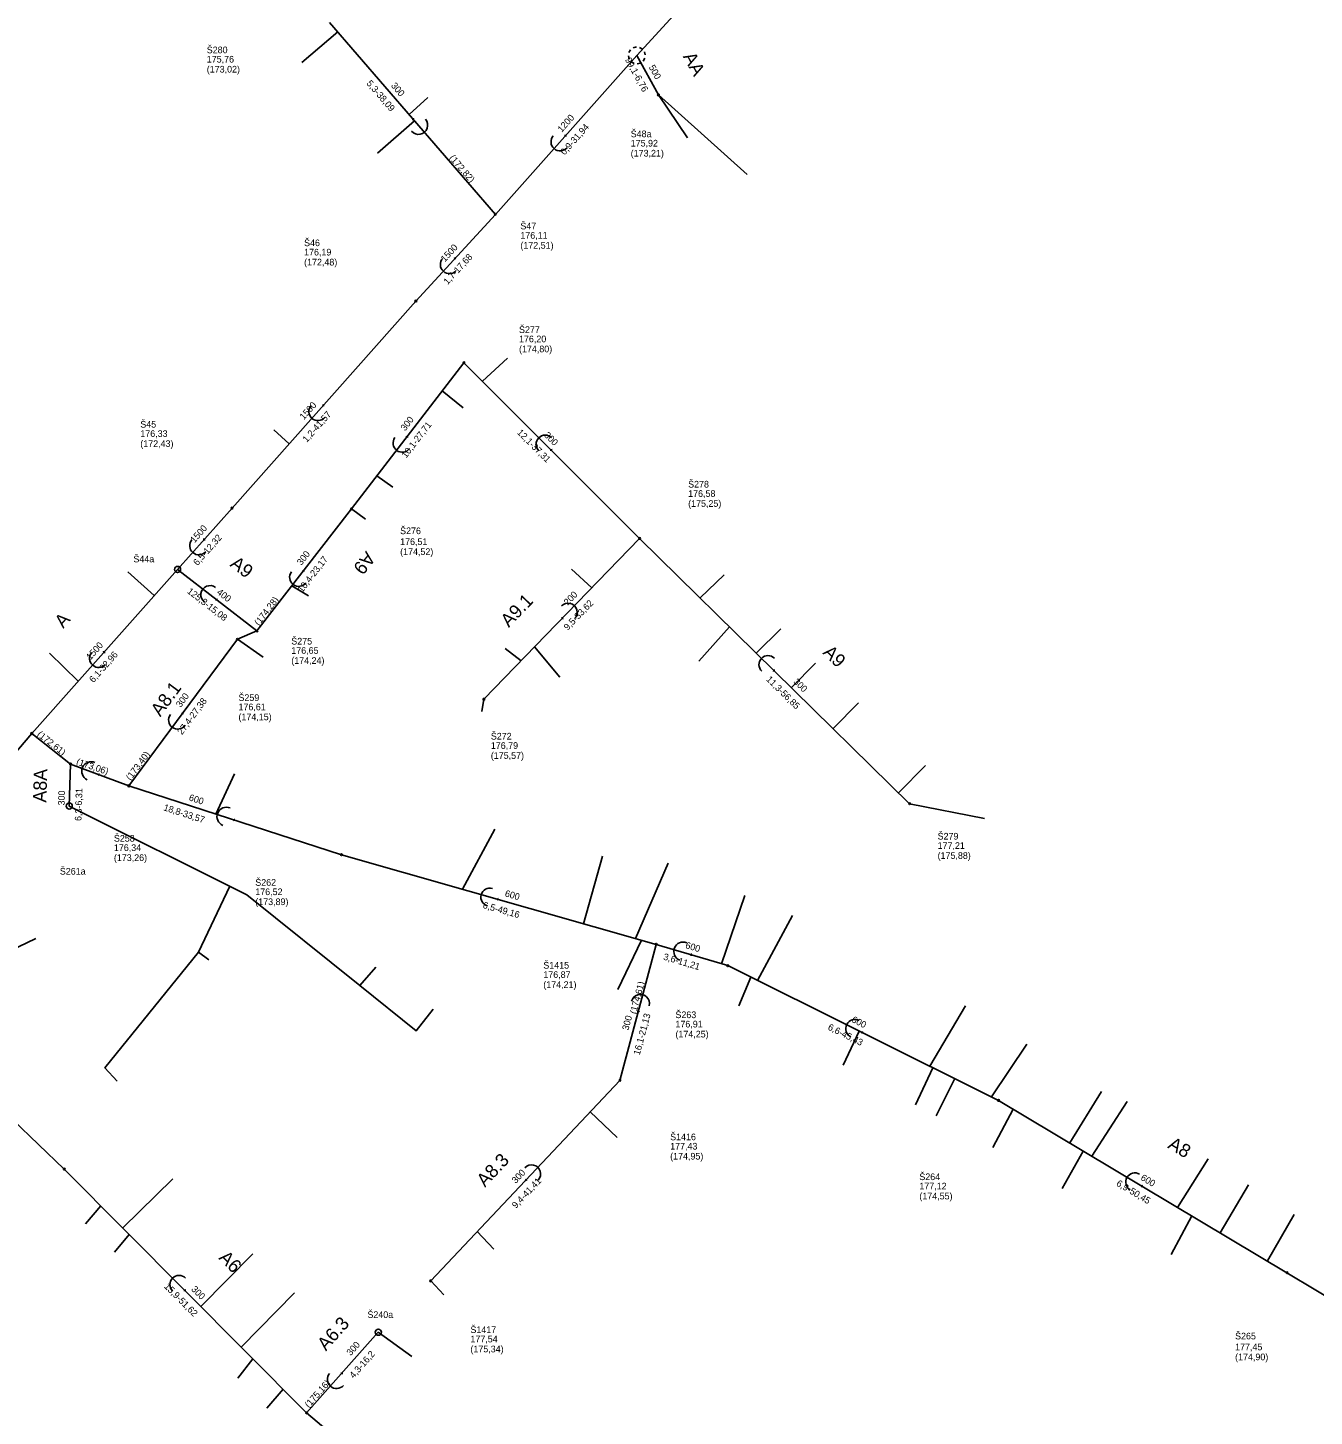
# Model space of a CAD drawing. Extents: x -548529 to -543591, y -1201432 to -1192608.
# Drawn here: x -544328 to -544134.8, y -1193048.7 to -1192840.3 of the extents above; entities that cross this region are included whole.
import ezdxf

# ---------------------------------------------------------------- set-up
doc = ezdxf.new("R2010")
doc.units = 0
for name, color, linetype in [('C3D_Bod-Značky', 7, 'Continuous'), ('C3D_Koridor', 7, 'Continuous'), ('C3D_Křižovatka', 7, 'Continuous'), ('C3D_Netisknutelná', 7, 'Continuous'), ('C3D_PP-zobrazeni v PR', 7, 'Continuous'), ('C3D_PR-Popisek', 7, 'Continuous'), ('C3D_SPR-Popisek', 7, 'Continuous'), ('C3D_Tlakove_potrubi_Popis', 7, 'Continuous'), ('C3D_ZPR-Formaty', 7, 'Continuous')]:
    doc.layers.add(name, color=color, linetype=linetype)

# ---------------------------------------------------------------- blocks, each defined once
blk = doc.blocks.new('100')
at = {"layer": 'Defpoints'}
blk.add_circle((0, 0), 0.127, dxfattribs=at)
blk = doc.blocks.new('102')
at = {"layer": 'Defpoints'}
for p, q in [((-1.17, -0.49), (-1.27, 0)), ((-1.17, 0.49), (-0.9, 0.9)), ((-0.49, 1.17), (0, 1.27)), ((0.49, 1.17), (0.9, 0.9)), ((1.17, 0.49), (1.27, 0)), ((-0.49, -1.17), (-0.9, -0.9)), ((0.49, -1.17), (0, -1.27)), ((1.17, -0.49), (0.9, -0.9))]:
    blk.add_line(p, q, dxfattribs=at)
blk = doc.blocks.new('101')
at = {"layer": 'Defpoints'}
blk.add_circle((0, 0), 0.463, dxfattribs=at)
blk = doc.blocks.new('91')
at = {"layer": 'Defpoints'}
blk.add_lwpolyline([(0.08, 0.14), (0.19, 0), (0.08, -0.14)], dxfattribs=at)
blk.add_arc((1.37, 0), 1.37, 270, 90, dxfattribs=at)
blk = doc.blocks.new('86')
at = {"layer": 'Defpoints'}
blk.add_lwpolyline([(0.08, 0.14), (0.19, 0), (0.08, -0.14)], dxfattribs=at)
blk.add_arc((1.37, 0), 1.37, 270, 90, dxfattribs=at)

msp = doc.modelspace()

# ---------------------------------------------------------------- linework, layer by layer
at = {"layer": 'C3D_Bod-Značky'}
for points in [[(-544213.325, -1192819.098), (-544236.511, -1192844.411)], [(-544282.66, -1192839.46), (-544257.75, -1192868.27)], [(-544236.511, -1192844.411), (-544257.75, -1192868.27)], [(-544233.256, -1192850.339), (-544236.511, -1192844.411)], [(-544257.75, -1192868.27), (-544269.702, -1192881.298)], [(-544269.702, -1192881.298), (-544297.304, -1192912.387)], [(-544262.47, -1192890.55), (-544279.368, -1192912.51)], [(-544236.09, -1192916.93), (-544262.47, -1192890.55)], [(-544297.304, -1192912.387), (-544305.491, -1192921.594)], [(-544279.368, -1192912.51), (-544293.566, -1192930.822)], [(-544259.476, -1192941.077), (-544236.09, -1192916.93)], [(-544195.529, -1192956.765), (-544236.09, -1192916.93)], [(-544305.491, -1192921.594), (-544327.39, -1192946.221)], [(-544293.566, -1192930.822), (-544305.491, -1192921.594)], [(-544293.566, -1192930.822), (-544296.51, -1192932.08)], [(-544296.51, -1192932.08), (-544312.81, -1192954.08)], [(-544327.39, -1192946.221), (-544355.66, -1192979.427)], [(-544321.558, -1192950.814), (-544327.39, -1192946.221)], [(-544321.759, -1192957.117), (-544321.558, -1192950.814)], [(-544312.81, -1192954.08), (-544321.558, -1192950.814)], [(-544280.876, -1192964.417), (-544312.81, -1192954.08)], [(-544233.591, -1192977.882), (-544280.876, -1192964.417)], [(-544239.04, -1192998.3), (-544233.591, -1192977.882)], [(-544222.846, -1192981.078), (-544233.591, -1192977.882)], [(-544182.172, -1193001.318), (-544222.846, -1192981.078)], [(-544322.5, -1193011.63), (-544345.72, -1192989.39)], [(-544267.47, -1193028.41), (-544239.04, -1192998.3)], [(-544138.857, -1193027.179), (-544182.172, -1193001.318)], [(-544286.1, -1193048.23), (-544322.5, -1193011.63)], [(-544095.329, -1193053.232), (-544138.857, -1193027.179)], [(-544275.341, -1193036.117), (-544286.1, -1193048.23)], [(-544277.47, -1193055.51), (-544286.1, -1193048.23)]]:
    msp.add_lwpolyline(points, dxfattribs=at)
at = {"layer": 'C3D_Koridor'}
for points in [[(-544281.437, -1192840.875), (-544286.837, -1192845.474)], [(-544233.256, -1192850.339), (-544219.943, -1192862.274)], [(-544233.256, -1192850.339), (-544228.897, -1192856.799)], [(-544270.717, -1192853.272), (-544267.878, -1192850.747)], [(-544269.899, -1192854.218), (-544275.454, -1192859.097)], [(-544259.704, -1192893.316), (-544255.956, -1192889.849)], [(-544265.727, -1192894.782), (-544262.591, -1192897.334)], [(-544288.715, -1192902.713), (-544291.047, -1192900.643)], [(-544275.549, -1192907.547), (-544273.146, -1192909.222)], [(-544279.368, -1192912.51), (-544277.276, -1192914.023)], [(-544243.255, -1192924.328), (-544246.325, -1192921.553)], [(-544308.98, -1192925.517), (-544312.965, -1192921.964)], [(-544226.984, -1192925.873), (-544223.374, -1192922.374)], [(-544288.308, -1192924.041), (-544285.802, -1192925.574)], [(-544222.588, -1192930.19), (-544227.201, -1192935.35)], [(-544218.572, -1192934.135), (-544214.893, -1192930.485)], [(-544296.51, -1192932.08), (-544292.646, -1192934.781)], [(-544253.886, -1192935.305), (-544256.298, -1192933.447)], [(-544251.877, -1192933.23), (-544248.065, -1192937.782)], [(-544320.424, -1192938.387), (-544324.702, -1192934.138)], [(-544213.278, -1192939.334), (-544209.667, -1192935.639)], [(-544259.476, -1192941.077), (-544259.811, -1192942.902)], [(-544207.04, -1192945.46), (-544203.224, -1192941.641)], [(-544299.742, -1192958.31), (-544296.938, -1192952.272)], [(-544197.198, -1192955.126), (-544193.153, -1192951.022)], [(-544195.529, -1192956.765), (-544184.267, -1192959)], [(-544321.759, -1192957.117), (-544295.103, -1192970.438), (-544278.127, -1192984.034), (-544275.696, -1192981.298)], [(-544262.689, -1192969.596), (-544257.822, -1192960.563)], [(-544244.524, -1192974.778), (-544241.642, -1192964.653)], [(-544236.703, -1192976.996), (-544231.792, -1192965.701)], [(-544297.646, -1192969.167), (-544302.359, -1192979.038), (-544300.802, -1192980.221)], [(-544223.795, -1192980.796), (-544220.308, -1192970.524)], [(-544218.368, -1192983.306), (-544213.114, -1192973.528)], [(-544337.14, -1192981.94), (-544326.769, -1192976.978)], [(-544235.789, -1192977.258), (-544239.342, -1192984.651)], [(-544302.359, -1192979.038), (-544316.408, -1192996.408), (-544314.577, -1192998.406)], [(-544278.127, -1192984.034), (-544269.629, -1192990.854), (-544267.101, -1192987.612)], [(-544219.407, -1192982.791), (-544221.168, -1192987.122)], [(-544192.502, -1192996.174), (-544187.147, -1192987.123)], [(-544203.095, -1192990.908), (-544205.54, -1192996.001)], [(-544183.256, -1193000.779), (-544177.905, -1192992.878)], [(-544192.037, -1192996.409), (-544194.649, -1193001.972)], [(-544188.752, -1192998.043), (-544191.555, -1193003.651)], [(-544171.476, -1193007.704), (-544166.718, -1192999.989)], [(-544179.959, -1193002.641), (-544183.034, -1193008.371)], [(-544168.186, -1193009.668), (-544162.837, -1193001.496)], [(-544243.524, -1193003.049), (-544239.481, -1193006.904)], [(-544169.458, -1193008.909), (-544172.61, -1193014.53)], [(-544155.282, -1193017.372), (-544150.71, -1193010.085)], [(-544313.711, -1193020.468), (-544306.192, -1193013.096)], [(-544148.875, -1193021.198), (-544144.653, -1193013.98)], [(-544317.023, -1193017.137), (-544319.3, -1193019.847)], [(-544153.171, -1193018.635), (-544156.239, -1193024.425)], [(-544141.8, -1193025.418), (-544137.798, -1193018.455)], [(-544312.737, -1193021.447), (-544314.959, -1193024.088)], [(-544260.467, -1193020.994), (-544257.989, -1193023.653)], [(-544302.009, -1193032.234), (-544294.2, -1193024.348)], [(-544267.47, -1193028.41), (-544265.49, -1193030.481)], [(-544295.92, -1193038.356), (-544287.93, -1193030.195)], [(-544275.341, -1193036.117), (-544270.281, -1193039.768)], [(-544294.182, -1193040.103), (-544296.446, -1193043.004)], [(-544289.626, -1193044.685), (-544292.057, -1193047.507)]]:
    msp.add_lwpolyline(points, dxfattribs=at)

# ---------------------------------------------------------------- block references
at = {"layer": 'C3D_PP-zobrazeni v PR'}
for name, p, xscale, yscale, rotation in [('102', (-544236.511, -1192844.411), 1.0000000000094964, 1.0000000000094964, -132.0000013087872), ('100', (-544233.256, -1192850.339), 1.0000000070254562, 1.0000000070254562, 118.99999892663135), ('100', (-544257.75, -1192868.27), 1.0000000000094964, 1.0000000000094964, -42.000001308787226), ('100', (-544269.702, -1192881.298), 1.0000000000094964, 1.0000000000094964, -132.0000013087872), ('100', (-544262.47, -1192890.55), 1.0000000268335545, 1.0000000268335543, -176.00000028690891), ('100', (-544297.304, -1192912.387), 1.0000000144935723, 1.0000000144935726, -130.99999910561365), ('100', (-544279.368, -1192912.51), 0.9999999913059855, 0.9999999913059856, -127.00000193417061), ('100', (-544236.09, -1192916.93), 1.000000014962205, 1.0000000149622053, 90.99999994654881), ('101', (-544305.491, -1192921.594), 1.0000000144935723, 1.0000000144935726, -130.99999910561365), ('100', (-544296.51, -1192932.08), 1.000000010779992, 1.0000000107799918, 38.9999989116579), ('100', (-544293.566, -1192930.822), 1.0092050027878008, 1.0092050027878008, -168.88308178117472), ('100', (-544259.476, -1192941.077), 1.0000000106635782, 1.0000000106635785, 45.99999834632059), ('100', (-544327.39, -1192946.221), 1.0000000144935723, 1.0000000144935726, -130.99999910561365), ('100', (-544321.558, -1192950.814), 1.000000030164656, 1.000000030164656, 114.99999971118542), ('100', (-544312.81, -1192954.08), 0.999999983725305, 0.999999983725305, 70.99999877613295), ('101', (-544321.759, -1192957.117), 1.000000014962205, 1.0000000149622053, -90.99999994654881), ('100', (-544195.529, -1192956.765), 1.0000000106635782, 1.0000000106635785, -44.00000165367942), ('100', (-544280.876, -1192964.417), 1.0365458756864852, 1.0365458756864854, -21.97149085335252), ('100', (-544233.591, -1192977.882), 1.019856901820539, 1.0198569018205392, 26.393983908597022), ('100', (-544222.846, -1192981.078), 1.0275072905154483, 1.027507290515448, -24.689105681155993), ('100', (-544239.04, -1192998.3), 1.0000000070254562, 1.0000000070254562, 61.000001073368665), ('100', (-544182.172, -1193001.318), 1.0072562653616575, 1.0072562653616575, 151.23333487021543), ('100', (-544322.5, -1193011.63), 1.0000000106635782, 1.0000000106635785, 135.99999834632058), ('100', (-544138.857, -1193027.179), 0.9999999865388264, 0.9999999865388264, 149.99999955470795), ('100', (-544267.47, -1193028.41), 1.00000000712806, 1.00000000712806, -133.00000056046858), ('101', (-544275.341, -1193036.117), 1.0000000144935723, 1.0000000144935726, 49.00000089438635), ('100', (-544286.1, -1193048.23), 1.0000000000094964, 1.0000000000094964, 137.9999986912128)]:
    msp.add_blockref(name, p, dxfattribs=dict(at, xscale=xscale, yscale=yscale, rotation=rotation))
at = {"layer": 'C3D_SPR-Popisek'}
for name, p, xscale, yscale, rotation in [('91', (-544270.205, -1192853.865), 1.0000000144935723, 1.0000000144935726, -49.00000089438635), ('91', (-544247.13, -1192856.34), 1.0000000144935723, 1.0000000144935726, -130.99999910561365), ('91', (-544263.726, -1192874.784), 1.0000000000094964, 1.0000000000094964, -132.0000013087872), ('91', (-544283.503, -1192896.842), 1.0000000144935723, 1.0000000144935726, -130.99999910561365), ('91', (-544270.919, -1192901.53), 0.9999999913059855, 0.9999999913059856, -127.00000193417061), ('91', (-544249.28, -1192903.74), 1.0000000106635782, 1.0000000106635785, 135.99999834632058), ('91', (-544301.398, -1192916.99), 1.0000000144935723, 1.0000000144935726, -130.99999910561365), ('91', (-544286.467, -1192921.666), 0.9999999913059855, 0.9999999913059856, -127.00000193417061), ('91', (-544299.528, -1192926.208), 0.9999999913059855, 0.9999999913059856, 142.99999806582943), ('91', (-544247.783, -1192929.004), 1.0000000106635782, 1.0000000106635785, 45.99999834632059), ('91', (-544316.441, -1192933.907), 1.0000000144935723, 1.0000000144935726, -130.99999910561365), ('91', (-544215.809, -1192936.847), 1.0000000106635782, 1.0000000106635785, 135.99999834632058), ('91', (-544304.66, -1192943.08), 1.000000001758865, 1.000000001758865, -125.99999933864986), ('91', (-544317.184, -1192952.447), 1.0296949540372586, 1.0296949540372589, 155.86620948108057), ('91', (-544296.843, -1192959.248), 1.035124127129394, 1.0351241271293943, 157.49634583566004), ('91', (-544257.234, -1192971.149), 0.999999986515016, 0.9999999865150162, 164.99999987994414), ('91', (-544228.218, -1192979.48), 1.0365458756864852, 1.0365458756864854, 158.02850914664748), ('86', (-544236.316, -1192988.091), 1.0000000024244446, 1.0000000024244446, 75.99999967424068), ('91', (-544202.509, -1192991.198), 1.0138865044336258, 1.0138865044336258, 152.43468640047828), ('86', (-544253.255, -1193013.355), 1.00000000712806, 1.00000000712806, 46.99999943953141), ('91', (-544160.514, -1193014.248), 0.9999999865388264, 0.9999999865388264, 149.99999955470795), ('91', (-544304.3, -1193029.93), 0.999999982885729, 0.9999999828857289, 135), ('91', (-544280.72, -1193042.174), 1.0000000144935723, 1.0000000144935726, -130.99999910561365)]:
    msp.add_blockref(name, p, dxfattribs=dict(at, xscale=xscale, yscale=yscale, rotation=rotation))

# ---------------------------------------------------------------- texts
at = {"layer": 'C3D_Křižovatka'}
for s, p in [('Š280', (-544301.1, -1192844.08)), ('Š48a', (-544237.426, -1192856.689)), ('Š47', (-544254, -1192870.53)), ('Š46', (-544286.482, -1192873.048)), ('Š277', (-544254.2, -1192886.08)), ('Š45', (-544311.084, -1192900.297)), ('Š278', (-544228.8, -1192909.29)), ('Š276', (-544272.058, -1192916.29)), ('Š44a', (-544312.121, -1192920.524)), ('Š275', (-544288.406, -1192932.862)), ('Š259', (-544296.34, -1192941.33)), ('Š272', (-544258.436, -1192947.127)), ('Š279', (-544191.329, -1192962.145)), ('Š258', (-544315.05, -1192962.46)), ('Š261a', (-544323.169, -1192967.407)), ('Š262', (-544293.816, -1192969.087)), ('Š1415', (-544250.551, -1192981.522)), ('Š263', (-544230.706, -1192988.958)), ('Š1416', (-544231.5, -1193007.29)), ('Š264', (-544194.072, -1193013.278)), ('Š240a', (-544276.971, -1193033.977)), ('Š1417', (-544261.5, -1193036.24)), ('Š265', (-544146.647, -1193037.199))]:
    msp.add_text(s, height=1, dxfattribs=at).set_placement(p)
at = {"layer": 'C3D_Netisknutelná'}
for s, rotation, p in [('AA', 298.77, (-544229.627, -1192844.574)), ('A9', 231.51, (-544277.174, -1192918.737)), ('A9', 322.27, (-544297.729, -1192921.014)), ('A9.1', 45.92, (-544255.741, -1192930.383)), ('A', 48.36, (-544322.662, -1192930.517)), ('A9', 315.52, (-544208.681, -1192934.181)), ('A8.1', 53.46, (-544308.081, -1192943.8)), ('A8A', 88.17, (-544325.217, -1192956.606)), ('A8', 329.16, (-544156.892, -1193008.377)), ('A8.3', 46.64, (-544259.319, -1193014.429)), ('A6', 314.84, (-544299.418, -1193025.057)), ('A6.3', 48.39, (-544283.2, -1193039.03))]:
    msp.add_text(s, height=2, rotation=rotation, dxfattribs=at).set_placement(p)
at = {"layer": 'C3D_PR-Popisek'}
for s, rotation, p in [('500', 298.77, (-544234.751, -1192846.158)), ('300', 310.85, (-544273.498, -1192848.991)), ('1200', 48.32, (-544247.791, -1192856.035)), ('1500', 47.47, (-544265.33, -1192875.494)), ('1500', 48.4, (-544286.52, -1192899.192)), ('300', 52.42, (-544271.298, -1192900.874)), ('300', 315, (-544250.514, -1192901.523)), ('1500', 48.36, (-544302.942, -1192917.68)), ('300', 52.21, (-544286.882, -1192921.05)), ('400', 322.27, (-544299.693, -1192925.188)), ('200', 45.92, (-544246.873, -1192927.054)), ('1500', 48.36, (-544318.566, -1192935.251)), ('300', 315.52, (-544213.075, -1192938.548)), ('300', 53.46, (-544305.029, -1192942.403)), ('300', 88.17, (-544322.457, -1192957.032)), ('600', 342.06, (-544303.874, -1192956.241)), ('600', 344.11, (-544256.407, -1192970.657)), ('600', 343.44, (-544229.296, -1192978.43)), ('300', 75.06, (-544237.778, -1192990.868)), ('600', 333.54, (-544204.342, -1192989.502)), ('300', 46.64, (-544254.688, -1193013.86)), ('600', 329.16, (-544160.925, -1193013.185)), ('300', 314.84, (-544303.51, -1193029.738)), ('300', 48.39, (-544279.476, -1193039.725))]:
    msp.add_text(s, height=1, rotation=rotation, dxfattribs=at).set_placement(p)
at = {"layer": 'C3D_Tlakove_potrubi_Popis'}
for s, p in [('(173,02)', (-544301.1, -1192846.98)), ('175,76 ', (-544301.1, -1192845.48)), ('(173,21)', (-544237.426, -1192859.589)), ('175,92 ', (-544237.426, -1192858.089)), ('176,11 ', (-544254, -1192871.93)), ('176,19 ', (-544286.482, -1192874.448)), ('(172,51)', (-544254, -1192873.43)), ('(172,48)', (-544286.482, -1192875.948)), ('(174,80)', (-544254.2, -1192888.98)), ('176,20 ', (-544254.2, -1192887.48)), ('176,33 ', (-544311.084, -1192901.697)), ('(172,43)', (-544311.084, -1192903.197)), ('176,58 ', (-544228.8, -1192910.69)), ('(175,25)', (-544228.8, -1192912.19)), ('176,51 ', (-544272.058, -1192917.92)), ('(174,52)', (-544272.058, -1192919.42)), ('176,65 ', (-544288.406, -1192934.262)), ('(174,24)', (-544288.406, -1192935.762)), ('176,61 ', (-544296.34, -1192942.73)), ('(174,15)', (-544296.34, -1192944.23)), ('176,79 ', (-544258.436, -1192948.527)), ('(175,57)', (-544258.436, -1192950.027)), ('176,34 ', (-544315.05, -1192963.86)), ('177,21 ', (-544191.329, -1192963.545)), ('(173,26)', (-544315.05, -1192965.36)), ('(175,88)', (-544191.329, -1192965.045)), ('176,52 ', (-544293.816, -1192970.487)), ('(173,89)', (-544293.816, -1192971.987)), ('176,87 ', (-544250.551, -1192982.922)), ('(174,21)', (-544250.551, -1192984.422)), ('176,91 ', (-544230.706, -1192990.358)), ('(174,25)', (-544230.706, -1192991.858)), ('177,43 ', (-544231.5, -1193008.69)), ('(174,95)', (-544231.5, -1193010.19)), ('(174,55)', (-544194.072, -1193016.178)), ('177,12 ', (-544194.072, -1193014.678)), ('(175,34)', (-544261.5, -1193039.14)), ('177,54 ', (-544261.5, -1193037.64)), ('177,45 ', (-544146.647, -1193038.829)), ('(174,90)', (-544146.647, -1193040.329))]:
    msp.add_text(s, height=1, dxfattribs=at).set_placement(p)
at = {"layer": 'C3D_ZPR-Formaty'}
for s, rotation, p in [('99,1-6,76', 298.77, (-544238.328, -1192845.045)), ('5,3-38,09', 310.85, (-544277.189, -1192848.653)), ('0,9-31,94', 48.32, (-544247.352, -1192859.447)), ('  (172,82)   ', 310.85, (-544265.251, -1192859.289)), ('1,7-17,68', 47.47, (-544264.93, -1192878.909)), ('1,2-41,57', 48.4, (-544286.077, -1192902.594)), ('10,1-27,71', 52.42, (-544271.159, -1192904.954)), ('12,1-37,31', 315, (-544254.572, -1192901.126)), ('6,5-12,32', 48.36, (-544302.501, -1192921.092)), ('10,4-23,17', 52.21, (-544286.756, -1192925.138)), ('125,3-15,08', 322.27, (-544304.137, -1192925.042)), ('  (174,28)   ', 52.21, (-544293.724, -1192930.699)), ('9,5-33,62', 45.92, (-544246.885, -1192930.807)), ('6,1-32,96', 48.36, (-544318.125, -1192938.663)), ('11,3-56,85', 315.52, (-544217.164, -1192938.18)), ('27,4-27,38', 53.46, (-544304.82, -1192946.487)), ('  (172,61)   ', 321.78, (-544327.266, -1192946.064)), ('  (173,06)   ', 341.51, (-544321.495, -1192950.624)), ('  (173,40)   ', 53.46, (-544312.971, -1192953.961)), ('6,3-6,31', 88.17, (-544319.93, -1192959.365)), ('18,8-33,57', 342.06, (-544307.682, -1192957.733)), ('6,5-49,16', 344.11, (-544259.717, -1192972.414)), ('3,6-11,21', 343.44, (-544232.613, -1192980.152)), ('  (174,61)   ', 75.06, (-544236.801, -1192989.135)), ('16,1-21,13', 75.06, (-544236.078, -1192994.582)), ('6,6-45,43', 333.54, (-544207.913, -1192990.633)), ('9,4-41,41', 46.64, (-544254.654, -1193017.604)), ('6,9-50,45', 329.16, (-544164.581, -1193014.033)), ('15,9-51,62', 314.84, (-544307.574, -1193029.331)), ('4,3-16,2', 48.39, (-544279.033, -1193043.127)), ('  (175,16)   ', 48.39, (-544286.25, -1193048.097))]:
    msp.add_text(s, height=1, rotation=rotation, dxfattribs=at).set_placement(p)

doc.saveas('drawing.dxf')
